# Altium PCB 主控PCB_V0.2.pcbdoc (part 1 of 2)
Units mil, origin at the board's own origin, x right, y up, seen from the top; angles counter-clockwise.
Board outline 2407.32 x 1620 mil, 2 copper layers (Top Layer, Bottom Layer); 44 components, 39 nets, 171 pads, 174 vias.
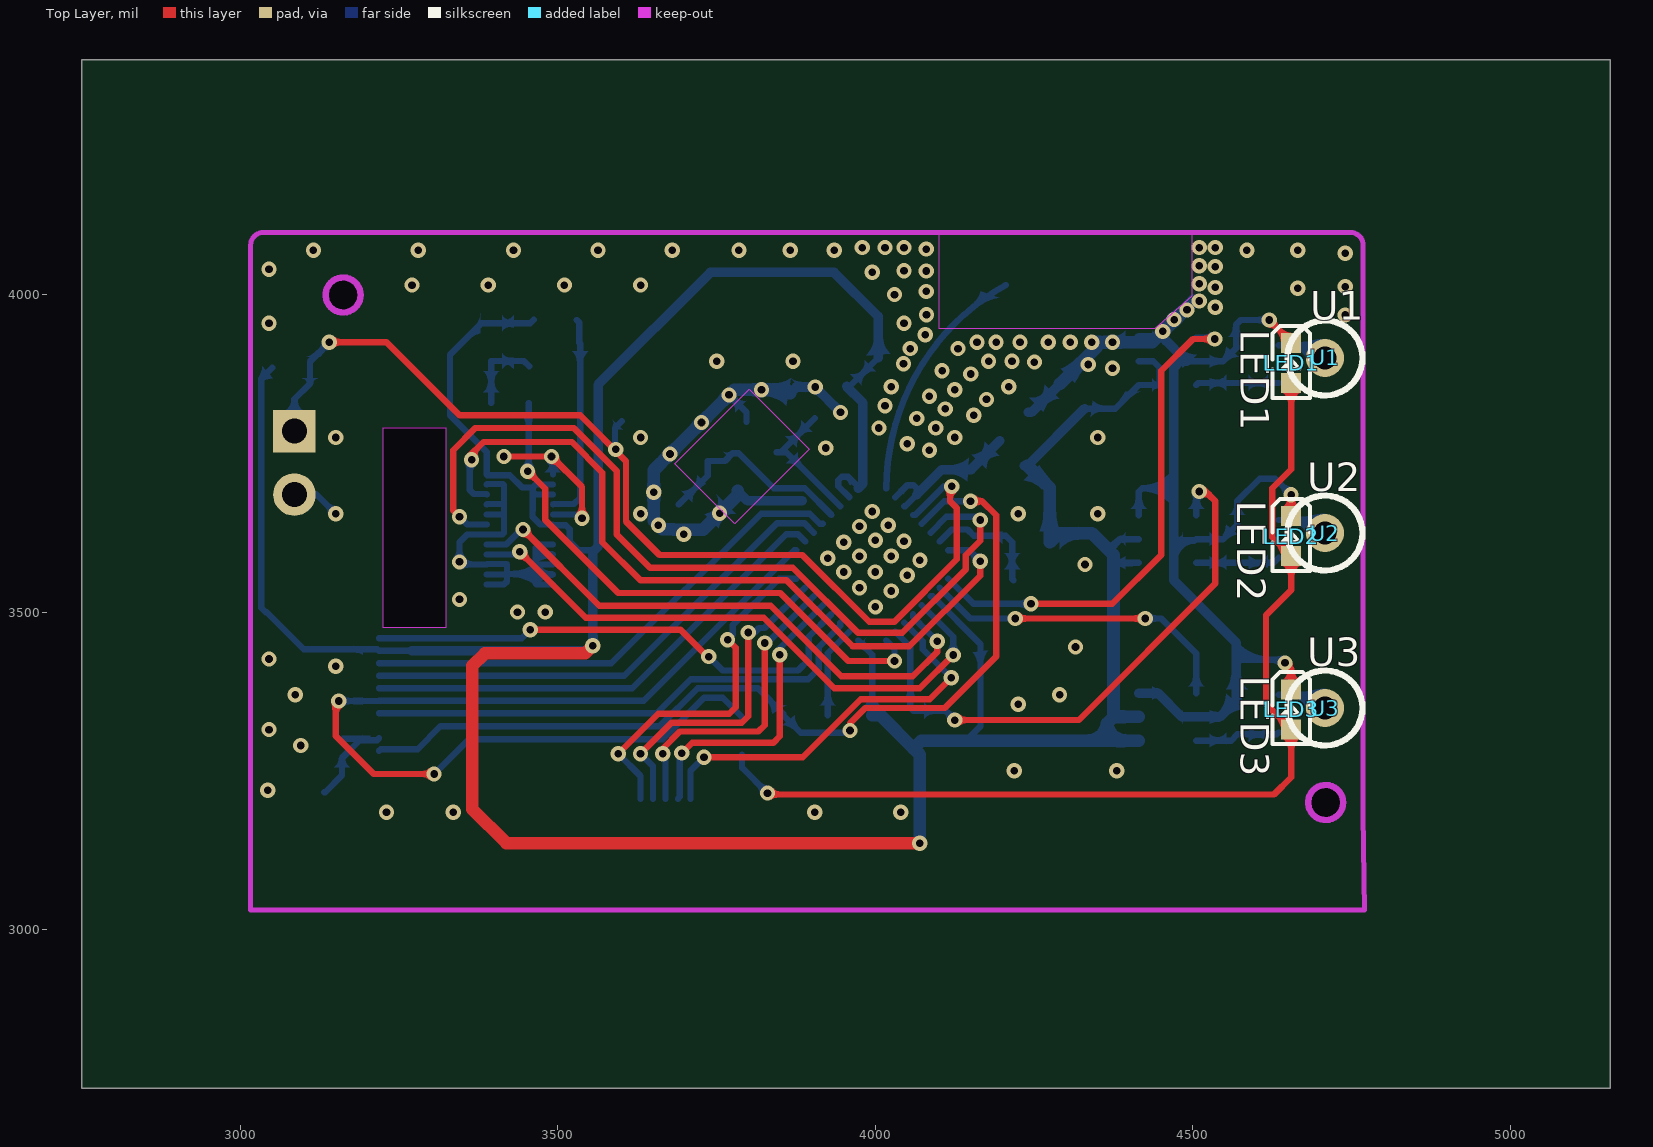
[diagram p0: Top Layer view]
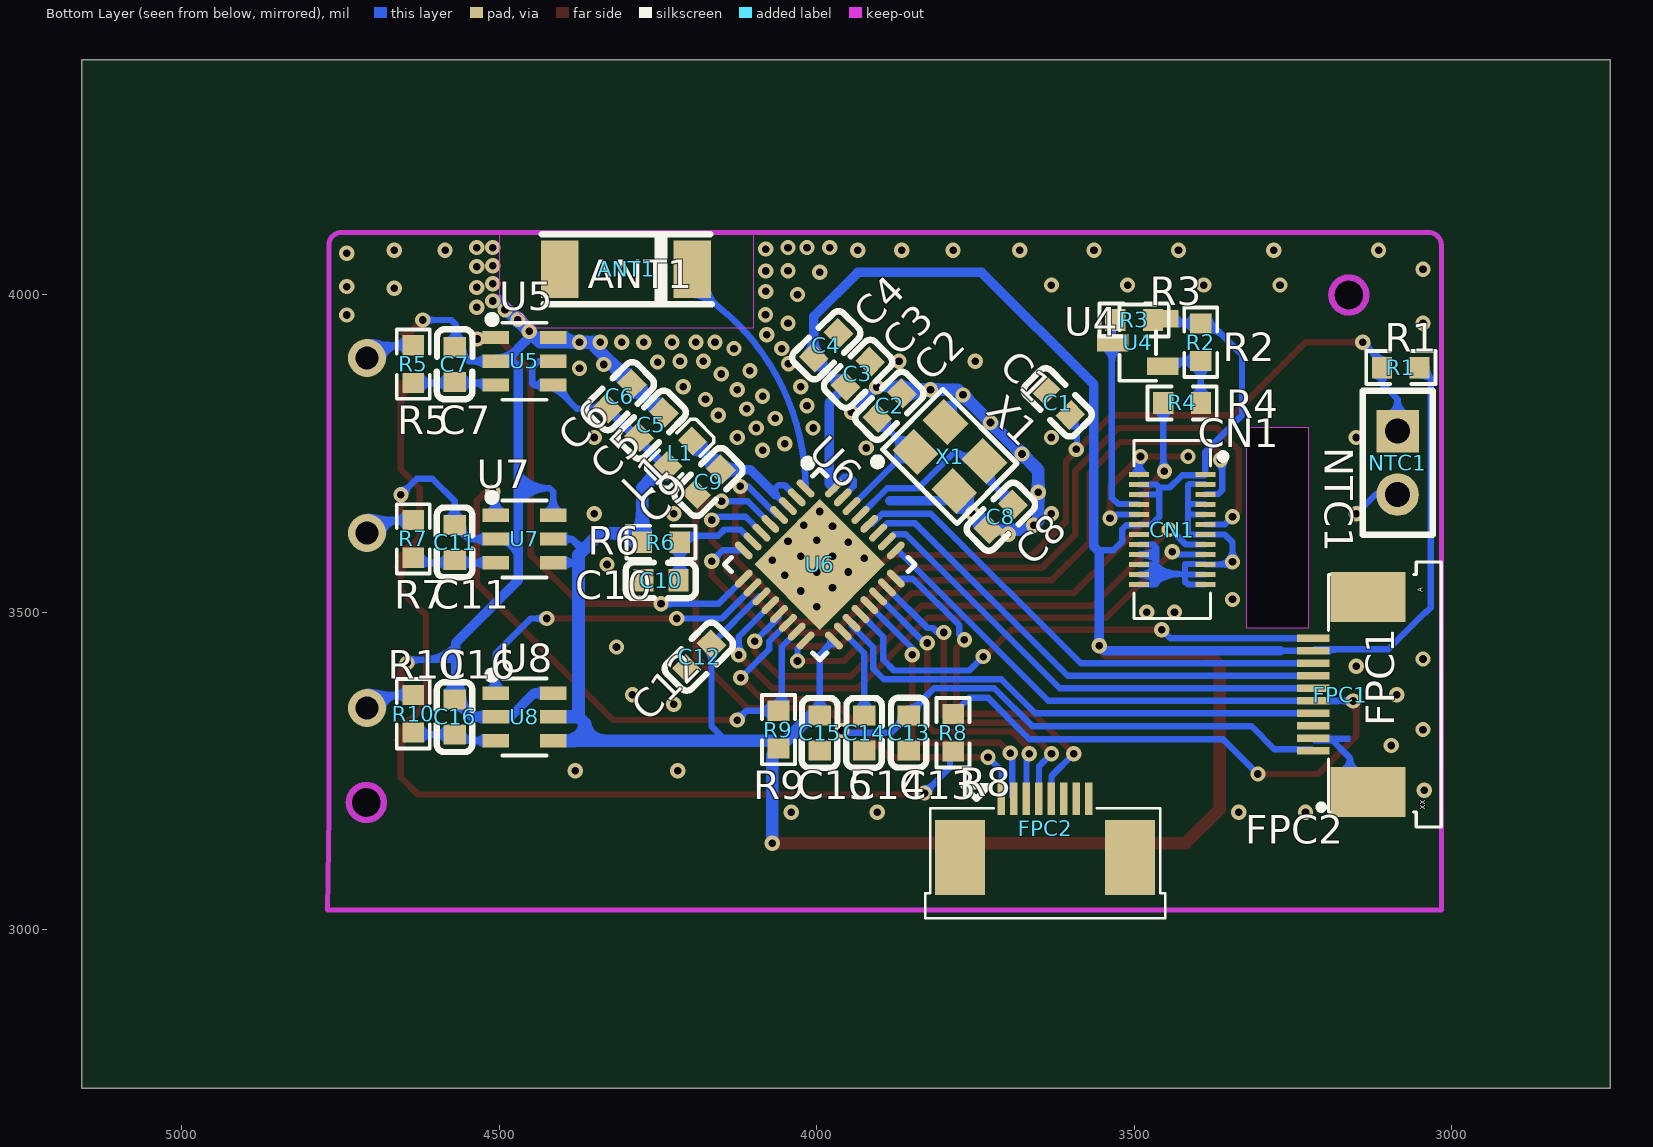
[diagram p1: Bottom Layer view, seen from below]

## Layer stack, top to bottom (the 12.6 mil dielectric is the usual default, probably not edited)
Top Layer: signal copper (thickness not stored)
Dielectric: dielectric 12.6, FR-4, Dk 4.8
Bottom Layer: signal copper (thickness not stored)

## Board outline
5157.32,2750 2750,2750 2750,4370 5157.32,4370
cut-out: 4736.57,3200.19 ccw(c4709.02,3199.82) 4681.46,3200.19 ccw(c4709.02,3200.56)
cut-out: 3189.33,3999.4 ccw(c3161.77,3999.4) 3134.21,3999.4 ccw(c3161.77,3999.4)
cut-out: 3225,3790 3323.43,3790 3323.43,3475.04 3225,3475.04

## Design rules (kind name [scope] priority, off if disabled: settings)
BoardOutlineClearance copperThickness1oz [All] p0: genericclearance=10 ignorepadtopadclearanceinfootprint=FALSE except(0: Arc-SplitContinuation Track-SplitContinuation SMDPad-SplitContinuation THPad-SplitContinuation Via-SplitContinuation Fill-SplitContinuation Poly-SplitContinuation Region-SplitContinuation Text-SplitContinuation; 6: Track-CutoutEdge SMDPad-CutoutEdge THPad-CutoutEdge Via-CutoutEdge Region-CutoutEdge; 11.8: Track-OutlineEdge SMDPad-OutlineEdge THPad-OutlineEdge Via-OutlineEdge Fill-OutlineEdge Region-OutlineEdge Poly-OutlineEdge Text-OutlineEdge Fill-CutoutEdge)
BoardOutlineClearance copperThickness2oz [All] p0: genericclearance=10 ignorepadtopadclearanceinfootprint=FALSE except(0: Arc-SplitContinuation Track-SplitContinuation SMDPad-SplitContinuation THPad-SplitContinuation Via-SplitContinuation Fill-SplitContinuation Poly-SplitContinuation Region-SplitContinuation Text-SplitContinuation; 6: Track-CutoutEdge SMDPad-CutoutEdge THPad-CutoutEdge Via-CutoutEdge Region-CutoutEdge; 11.8: Track-OutlineEdge SMDPad-OutlineEdge THPad-OutlineEdge Via-OutlineEdge Fill-OutlineEdge Region-OutlineEdge Poly-OutlineEdge Text-OutlineEdge Fill-CutoutEdge)
Clearance copperThickness1oz [(InNet('$1N1219') OR InNet('GND') OR InNet('3V3') OR InNet('$1N1185') OR InNet('$1N1981') OR InNet('$1N1223') OR InNet('$1N1184') OR InNet('CHIP_EN') OR InNet('VDD_SPI') OR InNet('$1N1977') OR InNet('$1N1980') OR InNet('GPIO0') OR InNet('GPIO6') OR InNet('GPIO7') OR InNet('GPIO2') OR InNet('K') OR InNet('GPIO3') OR InNet('ADC_VIN') OR InNet('ESP_TX') OR InNet('ESP_RX') OR InNet('GPIO13') OR InNet('GPIO12') OR InNet('DN1') OR InNet('DP1') OR InNet('$1N3691') OR InNet('$1N1982') OR InNet('$1N1983') OR InNet('$1N1984') OR InNet('GPIO9') OR InNet('$1N1544') OR InNet('BL') OR InNet('GPIO4') OR InNet('GPIO5') OR InNet('$1N7080') OR InNet('GPIO8') OR InNet('GPIO14') OR InNet('GPIO15') OR InNet('GPIO16') OR InNet('GPIO17'))] p1: gap=7 ignorepadtopadclearanceinfootprint=FALSE except(4: Track-Track; 6: Track-SMDPad SMDPad-SMDPad Track-THPad SMDPad-THPad THPad-THPad Track-Via SMDPad-Via THPad-Via Via-Via SMDPad-Fill THPad-Fill Via-Fill Fill-Fill Track-Region SMDPad-Region THPad-Region Via-Region Region-Region Track-Poly SMDPad-Poly THPad-Poly Via-Poly Fill-Poly Region-Poly Poly-Poly Track-Text SMDPad-Text THPad-Text Via-Text Fill-Text Region-Text Poly-Text Text-Text; 6.9: Track-Hole SMDPad-Hole THPad-Hole Via-Hole Fill-Hole Region-Hole Poly-Hole Text-Hole Sheet-Hole; 11.8: Track-Fill Fill-Region Track-Sheet SMDPad-Sheet THPad-Sheet Via-Sheet Fill-Sheet Region-Sheet Poly-Sheet Text-Sheet)
Clearance copperThickness2oz [All] p1: gap=7 ignorepadtopadclearanceinfootprint=FALSE except(6: Track-SMDPad SMDPad-SMDPad Track-THPad SMDPad-THPad THPad-THPad Track-Via SMDPad-Via THPad-Via Via-Via SMDPad-Fill THPad-Fill Via-Fill Fill-Fill Track-Region SMDPad-Region THPad-Region Via-Region Region-Region Track-Poly SMDPad-Poly THPad-Poly Via-Poly Fill-Poly Region-Poly Poly-Poly Track-Text SMDPad-Text THPad-Text Via-Text Fill-Text Region-Text Poly-Text Text-Text; 6.9: Track-Hole SMDPad-Hole THPad-Hole Via-Hole Fill-Hole Region-Hole Poly-Hole Text-Hole Sheet-Hole; 8: Track-Track; 11.8: Track-Fill Fill-Region Track-Sheet SMDPad-Sheet THPad-Sheet Via-Sheet Fill-Sheet Region-Sheet Poly-Sheet Text-Sheet)
DiffPairsRouting differentialPair [All] p1: maxuncoupledlength=10 minlimit=6 maxlimit=6 mostfreqgap=6 toplayer_minwidth=5 toplayer_prefwidth=10 toplayer_maxwidth=100 bottomlayer_minwidth=5 bottomlayer_prefwidth=10 bottomlayer_maxwidth=100
PasteMaskExpansion pasteMaskExpansion [All] p1: expansion=0
PlaneConnect innerPlane [All] p1: planeconnectstyle=Relief reliefexpansion=20 reliefentries=4 reliefconductorwidth=10 reliefairgap=10
PolygonConnect copperRegion [All] p1: connectstyle=Relief reliefentries=4 reliefconductorwidth=10 polygonreliefangle="90 Angle" airgapwidth=10
RoutingVias viaSize [All] p1: viastyle="Through Hole" holewidth=12.0078 minholewidth=11.811 maxholewidth=248.0314 width=24.0158 minwidth=19.685 maxwidth=393.7008
SolderMaskExpansion solderMaskExpansion [All] p1: useseparateexpansions=TRUE expansion=2 expansionbottom=2
Width copperThickness1oz [All] p1: maxlimit=100 minlimit=5 preferedwidth=10
Width copperThickness2oz [All] p1: maxlimit=100 minlimit=8 preferedwidth=10

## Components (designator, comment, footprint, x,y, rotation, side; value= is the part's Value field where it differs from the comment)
ANT1 "CA-C03" ANT-SMD_CA-C03 4300,4040 r180 bottom
C1 "CAP_0603" C0603 3620,3830 r225 bottom
C2 "CAP_0402" C0603 3885,3825 r135 bottom
C3 "CC0603KRX7R9BB104" C0603 3935,3875 r315 bottom
C4 "CL10A106MQ8NNNC" C0603 3985,3920 r315 bottom
C5 "CL10A105KB8NNNC" C0603 4260,3795 r315 bottom
C6 "CL10A106MQ8NNNC" C0603 4310,3840 r315 bottom
C7 "CAP_0603" C0603 4570,3890 r270 bottom
C8 "CAP_0402" C0603 3710,3650 r315 bottom
C9 "CC0603KRX7R9BB104" C0603 4170,3705 r135 bottom
C10 "CL10A105KB8NNNC" C0603 4245,3550 r180 bottom
C11 "CAP_0603" C0603 4570,3610 r90 bottom
C12 "CC0603KRX7R9BB104" C0603 4185,3430 r135 bottom
C13 "CAP_0603" C0603 3855,3310 r270 bottom
C14 "CL10A106MQ8NNNC" C0603 3925,3310 r90 bottom
C15 "CC0603KRX7R9BB104" C0603 3995,3310 r90 bottom
C16 "CAP_0603" C0603 4570,3335 r90 bottom
CN1 "DF37NC-24DS-0.4V(51)" CONN-SMD_DF37NC-24DS-0.4V-51 3440,3630 r270 bottom locked
FPC1 "F0501-T-10-20T-R" FPC-SMD_F0501-T-10-20T-R 3175,3370 r90 bottom locked
FPC2 "F0501-T-08-20T-R" FPC-SMD_8P-P0.50_L4.4-W9.6 3640,3160 r180 bottom
L1 "L_0402" l0603 4215,3750 r135 bottom
LED1 "LED_0603-B" LED_0603 4655,3890 r270 top locked
LED2 "LED_0603-B" LED_0603 4655,3617.5 r270 top locked
LED3 "LED_0603-B" LED_0603 4655,3345 r270 top locked
NTC1 "HDR-F_2.54_1x2P" HDR-TH_2P-P2.54-V-F 3085,3735 r270 bottom
R1 "Res_0603" R0603 3080,3885 r180 bottom
R2 "Res_0402" R0603 3395,3925 r270 bottom
R3 "Res_0402" R0603 3500,3960 r0 bottom
R4 "Res_0402" R0603 3424.33,3829.34 r180 bottom
R5 "Res_0603" R0603 4635,3890.56 r270 bottom
R6 "Res_0603" R0603 4245,3610 r180 bottom
R7 "Res_0603" R0603 4635,3615.28 r270 bottom
R8 "Res_0603" R0603 3785,3310 r270 bottom
R9 "Res_0603" R0603 4060,3315 r90 bottom
R10 "Res_0603" R0603 4635,3340 r270 bottom
U1 "触摸弹簧 H10.0mm" TH_H10.0MM 4707.91,3900.16 r0 top locked
U2 "触摸弹簧 H10.0mm" TH_H10.0MM 4707.91,3624.57 r0 top locked
U3 "触摸弹簧 H10.0mm" TH_H10.0MM 4707.91,3348.98 r0 top locked
U4 "AO3401A" SOT-23-3_L2.9-W1.3-P1.90-LS2.4-BR 3494.2,3924.34 r180 bottom
U5 "JL423B" SOT-23-6_L2.9-W1.6-P0.95-LS2.8-BL-2 4460,3895 r270 bottom
U6 "ESP32-C3FN4" QFN-32_L5.0-W5.0-P0.50-BL-EP3.7 3995,3575 r315 bottom locked
U7 "JL423B" SOT-23-6_L2.9-W1.6-P0.95-LS2.8-BL-2 4460,3615 r270 bottom
U8 "JL423B" SOT-23-6_L2.9-W1.6-P0.95-LS2.8-BL-2 4460,3335 r270 bottom
X1 "X322540MPB4SI" OSC-SMD_4P-L3.2-W2.5-BL_SIT8008BI 3790,3745 r225 bottom

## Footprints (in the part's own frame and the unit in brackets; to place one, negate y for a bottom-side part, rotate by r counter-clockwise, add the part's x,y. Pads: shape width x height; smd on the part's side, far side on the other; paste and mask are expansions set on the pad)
ANT-SMD_CA-C03 [mm]
  rect 1.5x2.3 smd: 1(-2.65,0) 2(2.65,0)
  silkscreen extent -3.37,-1.4 3.43,1.4
C0603 [mm]
  rect 0.8x0.9 smd: 1(-0.7,0) 2(0.7,0)
  silkscreen extent -1.41,-0.71 1.39,0.72
CONN-SMD_DF37NC-24DS-0.4V-51 [mm]
  rect 0.2x0.8 smd: 1(-2.2,1.325) 2(-2.2,-1.325) 3(-1.8,1.325) 4(-1.8,-1.325) 5(-1.4,1.325) 6(-1.4,-1.325) 7(-1,1.325) 8(-1,-1.325) 9(-0.6,1.325) 10(-0.6,-1.325) 11(-0.2,1.325) 12(-0.2,-1.325) 13(0.2,1.325) 14(0.2,-1.325) 15(0.6,1.325) 16(0.6,-1.325) 17(1,1.325) 18(1,-1.325) 19(1.4,1.325) 20(1.4,-1.325) 21(1.8,1.325) 22(1.8,-1.325) 23(2.2,1.325) 24(2.2,-1.325)
  silkscreen extent -3.56,-1.52 3.56,2.16
FPC-SMD_8P-P0.50_L4.4-W9.6 [mm]
  rect 2x3 smd: 0(-3.4,-1.175) 0(3.4,-1.175)
  rect 0.3x1.3 smd: 1(-1.75,1.175) 2(-1.25,1.175) 3(-0.75,1.175) 4(-0.25,1.175) 5(0.25,1.175) 6(0.75,1.175) 7(1.25,1.175) 8(1.75,1.175)
  silkscreen extent -4.8,-3.6 4.8,1.68
FPC-SMD_F0501-T-10-20T-R [mm]
  rect 0.3x1.3 smd: 1(-2.25,1.097) 2(-1.75,1.097) 3(-1.25,1.097) 4(-0.75,1.097) 5(-0.25,1.097) 6(0.25,1.097) 7(0.75,1.097) 8(1.25,1.097) 9(1.75,1.097) 10(2.25,1.097)
  rect 2x3 smd: 11(3.9,-1.097) 12(-3.9,-1.097)
  silkscreen extent -5.3,-4.03 5.3,0.87
HDR-TH_2P-P2.54-V-F [mm]
  rect 1.7x1.7 hole 1: 1(-1.27,0)
  round 1.7 hole 1: 2(1.27,0)
  silkscreen extent -2.88,-1.39 2.88,1.4
l0603 [mm]
  rect 0.8x0.864 smd: 1(-0.7,0) 2(0.7,0)
  silkscreen extent -1.42,-0.65 1.41,0.67
LED_0603 [mil]
  rect 31.5x31.5 smd: 1(-33.5,-0.4) 2(29.5,-0.2)
  silkscreen extent -61,-30 53,30
OSC-SMD_4P-L3.2-W2.5-BL_SIT8008BI [mm]
  rect 1.4x1.2 smd: 1(-1.1,-0.85) 2(1.1,-0.85) 3(1.1,0.85) 4(-1.1,0.85)
  silkscreen extent -2.1,-2.35 2.1,1.7
QFN-32_L5.0-W5.0-P0.50-BL-EP3.7 [mm]
  oval 0.28x0.9 smd: 1(-1.75,-2.55) 2(-1.25,-2.55) 3(-0.749,-2.55) 4(-0.249,-2.55) 5(0.249,-2.55) 6(0.749,-2.55) 7(1.25,-2.55) 8(1.75,-2.55) 17(1.75,2.55) 18(1.25,2.55) 19(0.749,2.55) 20(0.249,2.55) 21(-0.249,2.55) 22(-0.749,2.55) 23(-1.25,2.55) 24(-1.75,2.55)
  oval 0.9x0.28 smd: 9(2.55,-1.75) 10(2.55,-1.25) 11(2.55,-0.749) 12(2.55,-0.249) 13(2.55,0.249) 14(2.55,0.749) 15(2.55,1.25) 16(2.55,1.75) 25(-2.55,1.75) 26(-2.55,1.25) 27(-2.55,0.749) 28(-2.55,0.249) 29(-2.55,-0.249) 30(-2.55,-0.749) 31(-2.55,-1.25) 32(-2.55,-1.75)
  rect 3.7x3.7 smd: 33(0,0)
  silkscreen extent -2.7,-3.35 2.7,2.7
R0603 [mil]
  rect 31.75x34.02 smd: 1(-29.66,0) 2(29.66,0)
  silkscreen extent -55,-26 55,26
SOT-23-3_L2.9-W1.3-P1.90-LS2.4-BR [mm]
  rect 1.25x0.7 smd: 1(1,-0.95) 2(1,0.95) 3(-1,0)
  silkscreen extent -0.73,-1.53 0.73,1.53
SOT-23-6_L2.9-W1.6-P0.95-LS2.8-BL-2 [mil]
  rect 20.95x42.2 smd: 1(-37.4,-45.24) 2(0,-45.24) 3(37.4,-45.24) 4(37.4,45.24) 5(0,45.24) 6(-37.4,45.24)
  silkscreen extent -72,-57 61,35
TH_H10.0MM [mil]
  round 60 hole 36: 1(0,0)
  silkscreen extent -59,-59 59,59

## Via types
v1: diameter 24.02, hole 12.01, Top Layer to Bottom Layer, 174 vias

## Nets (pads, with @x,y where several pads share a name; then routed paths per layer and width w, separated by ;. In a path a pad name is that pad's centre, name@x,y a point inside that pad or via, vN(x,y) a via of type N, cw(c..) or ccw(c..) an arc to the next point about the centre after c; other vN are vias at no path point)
3V3: C3.2 C4.2 C5.2 C6.2 C12.2 C15.2 CN1.1 CN1.4 CN1.6 CN1.12 FPC1.9 L1.1 R1.2 R2.1 R3.1 R6.1 R9.1 U4.2 U5.4 U5.5 U6.11 U6.17 U6.31 U6.32 U7.4 U7.5 U8.4 U8.5 | length 6142.6
  Top Layer w20: v1(3555,3447.21) 3542.79,3435 3385,3435 3365,3415 3365,3190 3418.82,3136.18 v1(4069.85,3136.18)
  Bottom Layer w10: 3032.92,3867.58 R1.2@3050.34,3885 ; 3032.93,3867.58 3032.93,3507.07 3040,3500 3041.41,3500 3099.71,3441.7 3215.38,3441.7 FPC1.9@3218.18,3438.89 3270,3438.89 ; R3.1@3462.13,3960.14 3456.64,3954.66 3379.66,3954.66 3330,3905 3330,3810 3387.84,3752.16 CN1.1@3387.84,3716.61 3388.66,3715.79 3424.21,3715.79 3443.75,3696.25 3460.39,3696.25 ; CN1.6@3492.16,3685.11 3465,3685.11 3460.39,3689.73 ; CN1.4@3492.16,3700.86 3465,3700.86 3460.39,3696.25 ; 3557.5,3597.5 3532.54,3597.5 3518.9,3611.14 3518.9,3630.61 3512.46,3637.05 3492.99,3637.05 CN1.12@3492.16,3637.88 3472.12,3637.88 3460,3650 3460,3660 3460.39,3660.39 3460.39,3689.73 ; C3.2@3954.49,3855.51 3959.49,3855.51 C4.2@4004.49,3900.51 ; U6.31@3958.8,3680.78 3958.8,3681.2 3941.59,3698.41 3941.59,3707.45 3947.07,3712.93 3957.07,3712.93 3972.73,3697.27 U6.32@3972.73,3694.71 ; U6.17@3972.73,3455.29 3995,3433.01 C15.2@3995,3340 ; U6.11@4086.85,3524.87 4090.13,3524.87 C12.2@4165.51,3449.49 4165.51,3320.51 4142.6,3297.6 ; C6.2@4329.49,3820.51 4377.67,3820.51 U5.4@4414.76,3857.6 4445.2,3857.6 4447.6,3860 4447.6,3885 4437.6,3895 U5.5@4414.76,3895 ; 4366.57,3598.43 4368.43,3598.43 4385,3615 U7.5@4414.76,3615 ; 4375,3577.05 4375.55,3577.6 U7.4@4414.76,3577.6 ; 3460.39,3689.73 3460.39,3696.25
  Bottom Layer w15: 3270,3438.89 3546.69,3438.89 v1(3555,3447.21) 3555,3595 3557.5,3597.5 3563.36,3603.36 3563.36,3858.36 3740,4035 3935,4035 4004.49,3965.51 C4.2@4004.49,3900.51 ; C3.2@3954.49,3855.51 3980,3830 3980,3701.99 U6.32@3972.73,3694.71 ; C15.2@3995,3337.56 C15.2@3995,3340 ; L1.1@4234.48,3730.52 4239.49,3730.52 C6.2@4329.49,3820.51
  Bottom Layer w20: C15.2@3995,3337.56 4007.78,3337.56 R9.1@4060,3285.34 ; v1(4069.85,3136.18) 4069.85,3275.49 R9.1@4060,3285.34 ; L1.1@4239.49,3730.52 4274.66,3695.35 R6.1@4274.66,3610 4288.8,3624.14 4340.86,3624.14 4366.57,3598.43 4375,3590 4375,3577.05 4375,3335 ; U8.4@4414.76,3297.6 4364.65,3297.6 ; U8.5@4414.76,3335 4375,3335 ; R9.1@4060,3285.34 4060.34,3285.34 4072.6,3297.6 4142.6,3297.6 4364.65,3297.6 ; 4364.65,3297.6 4364.65,3324.65 4375,3335
$1N1184: C8.1 U6.29 X1.3 | length 327.7
  Bottom Layer w10: C8.1@3690.51,3669.49 3735.71,3714.69 X1.3@3735.71,3738.04 3763.04,3738.04 3775,3750 3785,3750 3840,3695 3888.86,3695 U6.29@3930.94,3652.92
$1N1185: C2.1 U6.30 X1.1 | length 211.6
  Bottom Layer w10: X1.1@3844.29,3751.96 X1.1@3850.94,3751.96 ; C2.1@3904.49,3805.51 X1.1@3850.94,3751.96 ; U6.30@3944.87,3666.85 3859.76,3751.96 X1.1@3850.94,3751.96
$1N1219: ANT1.2 U6.1 | length 389.2
  Bottom Layer w10: U6.1@4017.27,3694.71 cw(c4384.36,3694.71) ANT1.2@4205,4015
$1N1223: C9.2 L1.2 U6.2 U6.3 | length 246.7
  Bottom Layer w10: U6.2@4031.2,3680.78 4050.42,3700 4060,3700 4065,3695 4065,3685 4046.85,3666.85 U6.3@4045.13,3666.85
  Bottom Layer w15: 4065,3685 4104.49,3724.49 C9.2@4150.51,3724.49 L1.2@4195.52,3769.48
$1N1544: R2.2 R4.2 U4.1 | length 129.4
  Bottom Layer w10: R4.2@3394.67,3829.34 3395,3829.68 R2.2@3395,3895.34 3446.43,3895.34 U4.1@3454.83,3886.94
$1N1977: C7.2 R5.2 U5.3 | length 131.1
  Bottom Layer w10: U5.3@4505.24,3857.6 4508.54,3860.9 R5.2@4635,3860.9
$1N1980: C16.1 R10.2 U8.3 | length 135
  Bottom Layer w10: U8.3@4505.24,3297.6 4560.16,3297.6 C16.1@4570,3307.44 4632.1,3307.44 R10.2@4635,3310.34
$1N1981: C11.1 R7.2 U7.3 | length 133.1
  Bottom Layer w10: U7.3@4505.24,3577.6 4626.98,3577.6 R7.2@4635,3585.62
$1N1982: R5.1 U1.1 | length 81.2
  Bottom Layer w10: R5.1@4635,3920.22 4687.85,3920.22 U1.1@4707.91,3900.16
$1N1983: R10.1 U3.1 | length 81.5
  Bottom Layer w10: R10.1@4635,3369.66 4687.23,3369.66 U3.1@4707.91,3348.98
$1N1984: R7.1 U2.1 | length 81.4
  Bottom Layer w10: R7.1@4635,3644.94 4687.54,3644.94 U2.1@4707.91,3624.57
$1N3691: LED1.2 LED2.2 LED3.2 R8.2 | length 1592.2
  Top Layer w10: v1(3830,3215) 3832.3,3212.7 4627.7,3212.7 4654.8,3239.8 LED3.2@4654.8,3315.5 4615,3355.3 4615,3495 4654.8,3534.8 LED2.2@4654.8,3588 4625,3617.8 4625,3695 4654.8,3724.8 LED1.2@4654.8,3860.5
  Bottom Layer w10: R8.2@3790,3275.34 3790,3255 v1(3830,3215)
$1N7080: FPC1.3
ADC_VIN: C13.1 FPC1.1 U6.5 | length 1463
  Top Layer w10: v1(3960,3313.65) 3960,3325 3983.98,3348.98 4108.98,3348.98 4190,3430 4190,3652.52 4167.77,3674.75 v1(4149.75,3674.75)
  Bottom Layer w10: FPC1.1@3218.18,3281.41 3220.98,3284.22 3279.22,3284.22 3315,3320 3660,3320 3720,3380 3815,3380 3855,3340 C13.1@3855,3337.56 3882.56,3310 3956.35,3310 v1(3960,3313.65) ; U6.5@4072.92,3639.06 4108.61,3674.75 v1(4149.75,3674.75)
BL: R4.1 U6.16 | length 876
  Top Layer w10: v1(3452.29,3721.87) 3480,3694.15 3480,3645 3595,3530 3850,3530 3957.01,3422.99 v1(4030,3422.99)
  Bottom Layer w10: v1(3452.29,3721.87) 3453.99,3723.57 R4.1@3453.99,3829.34 ; U6.16@4017.27,3455.29 4030,3442.56 v1(4030,3422.99)
CHIP_EN: C10.2 R6.2 U6.7 | length 191.5
  Bottom Layer w10: U6.7@4100.78,3611.2 4101.2,3611.2 4120,3630 4145,3630 4155,3620 4205.34,3620 R6.2@4215.34,3610 4215.34,3552.1 C10.2@4217.44,3550
DN1: FPC1.5 R8.1 U6.25 | length 1602.8
  Top Layer w10: v1(3155,3360) 3150,3355 3150,3305 3210,3245 v1(3305,3245)
  Bottom Layer w10: v1(3155,3360) 3218.02,3360 FPC1.5@3218.18,3360.16 3635.16,3360.16 3872.27,3597.27 U6.25@3875.29,3597.27 ; v1(3305,3245) 3360,3300 3665,3300 3730,3365 3759.66,3365 R8.1@3790,3334.66
DP1: FPC1.6 U6.26 | length 776.1
  Bottom Layer w10: FPC1.6@3218.18,3379.84 3617.27,3379.84 3859.82,3622.4 3878.02,3622.4 U6.26@3889.22,3611.2
ESP_RX: FPC1.7 U6.27 | length 790.7
  Bottom Layer w10: FPC1.7@3218.18,3399.53 3604.53,3399.53 3845,3640 3888.28,3640 U6.27@3903.15,3625.13
ESP_TX: FPC1.8 U6.28 | length 803.2
  Bottom Layer w10: FPC1.8@3218.18,3419.22 3584.22,3419.22 3820,3655 3896.61,3655 3912.55,3639.06 U6.28@3917.08,3639.06
GND: C1.1 C2.2 C3.1 C4.1 C5.1 C6.1 C7.1 C8.2 C9.1 C10.1 C11.2 C12.1 C13.2 C14.1 C15.1 C16.2 CN1.2 CN1.3 CN1.7 CN1.9 CN1.10 CN1.13 CN1.16 CN1.18 CN1.19 CN1.20 CN1.21 CN1.22 CN1.23 CN1.24 FPC1.2 FPC1.11 FPC1.12 FPC2.0 LED1.1 LED2.1 LED3.1 NTC1.2 U5.2 U5.6 U6.33 U7.2 U7.6 U8.2 U8.6 X1.2 X1.4 | length 3883.7
  Top Layer w10: v1(3415,3745) v1(3490,3745) 3537.87,3697.13 v1(3537.87,3647.85) ; v1(4620,3960) 4654.6,3925.4 LED1.1@4654.6,3923.5 ; v1(4645,3420) 4654.6,3410.4 LED3.1@4654.6,3378.5 ; LED2.1@4654.6,3651 v1(4654.6,3685)
  Top Layer w20: v1(4225,3655) v1@4225.08,3654.92
  Bottom Layer w10: NTC1.2@3085,3685 3120.12,3685 v1(3150.2,3654.92) ; FPC1.12@3131.82,3216.45 3133.53,3216.45 3160,3242.93 3160,3270.27 3188.04,3298.3 3215.38,3298.3 FPC1.2@3218.18,3301.11 ; CN1.23@3387.84,3543.39 3415,3543.39 3419.87,3548.25 3419.87,3560.06 ; CN1.21@3387.84,3559.14 3418.94,3559.14 3419.87,3560.06 ; CN1.9@3387.84,3653.62 3413.62,3653.62 3415,3655 ; CN1.7@3387.84,3669.38 3388.65,3670.19 3414.81,3670.19 3415,3670 ; CN1.3@3387.84,3700.86 3388.66,3701.69 3413.31,3701.69 3415,3700 3415,3670 ; 3419.93,3560 3464.94,3560 ; 3464.94,3545.06 3464.94,3560 ; 3464.94,3574.89 3464.94,3560 ; 3465,3545 3466.61,3543.39 CN1.24@3492.16,3543.39 ; 3465.2,3580.1 3465.2,3601.58 3470,3606.38 CN1.16@3492.16,3606.38 ; 3465.86,3559.14 CN1.22@3492.16,3559.14 ; 3465.84,3590.64 CN1.18@3492.16,3590.64 ; 3470,3574.89 CN1.20@3492.16,3574.89 ; v1(3490,3745) 3492.16,3742.84 CN1.2@3492.16,3716.61 ; CN1.10@3492.16,3653.62 3532.1,3653.62 v1(3537.87,3647.85) ; v1(3769.52,3842.02) 3796.96,3814.58 X1.4@3796.96,3799.29 ; U7.6@4414.76,3652.4 4414.76,3689.76 4420,3695 4467.58,3695 4470,3692.58 ; 4470,3620 4477.07,3612.93 4503.17,3612.93 U7.2@4505.24,3615 4547.44,3615 C11.2@4570,3637.56 4570,3675 4605,3710 4629.6,3710 v1(4654.6,3685) ; U5.2@4490,3895 U5.2@4505.24,3895 4547.44,3895 C7.1@4570,3917.56 4567.93,3919.63 4567.93,3952.93 4575,3960 v1(4620,3960) ; 4567.93,3417.93 4575,3425 4640,3425 v1(4645,3420) ; 3415,3655 3415,3670 ; 3415,3655 3415,3625 3412.12,3622.12 CN1.13@3387.84,3622.12 3357.12,3622.12 3345,3610 v1(3345,3579.03) 3349.14,3574.89 CN1.19@3387.84,3574.89 3388.66,3575.71 3419.15,3575.71 3419.87,3575 3419.87,3560.06
  Bottom Layer w15: X1.2@3783.04,3690.71 3798.75,3675 3885,3675 ; C2.2@3865.51,3844.49 3875.51,3854.49 v1(3905.21,3854.49) 3905.21,3854.29 v1(3945.06,3814.44) ; C5.1@4240.51,3814.49 4245.51,3814.49 C6.1@4290.51,3859.49 ; U8.6@4414.76,3372.4 4445,3372.4 4482.4,3335 U8.2@4505.24,3335 4542.44,3335 C16.2@4570,3362.56 4567.93,3364.63 4567.93,3417.93 4567.93,3452.07 4470,3550 4470,3620 4470,3692.58 4470,3885 4480,3895 4490,3895 4452.6,3932.4 4442.98,3932.4 U5.6@4414.76,3932.4
  Bottom Layer w20: X1.2@3783.04,3690.71 3783.04,3684.06 v1(3754.62,3655.64) C8.2@3729.49,3630.51 3728.82,3629.84 3682.5,3629.84 3681.83,3630.51 3664.49,3630.51 3650.86,3644.14 v1(3650.86,3688.7) 3650.86,3723.36 v1(3676.42,3748.92) v1(3726.15,3798.65) v1(3769.52,3842.02) 3777.5,3850 v1(3820.55,3850) 3860,3850 C2.2@3865.51,3844.49 ; C6.1@4290.51,3859.49 v1@4348.43,3917.4 ; v1(4340.83,3925) v1(4373.35,3925) 4435.58,3925 4442.98,3932.4 v1(4452.6,3942.02) 4500.58,3990 v1(4510,3990)
  other v1: 3230,3185 3335,3185 3904.26,3185 4040,3185 3043.21,3219.55 4218.54,3250 4380,3250 3095,3290 3045,3315 4225,3355 3086.42,3370 4290,3370 3150.2,3414.92 3045,3426.12 4315,3445 3436.41,3500 3480,3500 4000,3508.24 3345,3520 4025,3533.24 3974.91,3538.24 4050,3558.24 3950,3563.24 3999.91,3563.24 4330,3575 4070,3581.76 3925,3585 3975,3588.24 4024.91,3588.24 3950,3610 4044.91,3611.76 4000,3613.24 3698.05,3622.44 3975,3635 3658.27,3636.73 4020,3636.76 3630.2,3654.92 4350.2,3654.92 3995,3658.52 4085,3755 3921.79,3758.47 4050,3765 3150.2,3774.92 3630.2,3774.92 4125,3775 4350.2,3774.92 4005.49,3789.95 4095,3790 4065,3805 4155,3810 4110,3820 4015,3825 4175,3835 4085,3840 4125,3850 4025,3855 4210,3855 4150,3875 4105,3880 4373.35,3883.83 4335,3890 4044.23,3891.07 4250.33,3893.68 3750.2,3894.92 3870.2,3894.92 4178.21,3895 4215,3895 4055,3915 4130,3915 4160,3925 4189.99,3925 4227.7,3925 4272.01,3925 4306.89,3925 4078.34,3936.61 3045,3955 4045,3955 4470.32,3960.6 4080.49,3968.29 4740,3967.89 4490.56,3975.86 4535,3980.01 4030,4000 4080,4005 4665,4010 4535,4011.31 4740,4012.65 3270.2,4014.92 3390.2,4014.92 3510.2,4014.92 3630.2,4014.92 4510,4017.02 3995,4035 4080,4037.23 4045,4037.56 3045,4040 4535,4044.12 4510,4045.3 4740,4065 3115,4070 3280,4070 3430,4070 3563.06,4070 3680,4070 3785,4070 3865.68,4070 3935,4070 4585,4070 4665,4070 4080,4071.64 3979.28,4074 4015,4074 4045,4074 4510,4074 4535,4074
GPIO0: C1.2 NTC1.1 R1.1 U6.4 | length 1679.1
  Top Layer w10: v1(3140,3925) 3230,3925 3345,3810 3535,3810 3607.21,3737.79 3607.21,3642.79 3660,3590 3885,3590 3990,3485 4030,3485 4127.99,3582.99 4127.99,3663.99 4117.5,3674.48 4117.5,3695.49 v1(4120,3697.99)
  Bottom Layer w10: NTC1.1@3085,3785 3085,3835 3109.66,3859.66 R1.1@3109.66,3885 3109.66,3894.66 v1(3140,3925) ; v1@3590,3755 3590,3790 C1.2@3600.51,3800.51 ; U6.4@4059.06,3652.92 4062.92,3652.92 4107.99,3697.99 v1(4120,3697.99)
  other v1: 3591.26,3756.26
GPIO2: CN1.11 U6.6 | length 1389.9
  Top Layer w10: v1(3345,3650) 3335,3660 3335,3755 3370,3790 3525,3790 3592.75,3722.25 3592.75,3622.25 3645,3570 3870,3570 3972.5,3467.5 4042.5,3467.5 4142.01,3567.01 4142.01,3589.52 4165,3612.52 v1(4165,3645)
  Bottom Layer w10: v1(3345,3650) 3357.12,3637.88 CN1.11@3387.84,3637.88 ; U6.6@4086.85,3625.13 4111.72,3650 4160,3650 v1(4165,3645)
GPIO3: CN1.5 U6.8 | length 1220.1
  Top Layer w10: v1(3364.09,3740) 3364.09,3749.09 3382.99,3767.99 3521.53,3767.99 3570,3719.52 3570,3610 3630,3550 3860,3550 3964.02,3445.98 4053.47,3445.98 4165,3557.52 v1(4165,3580)
  Bottom Layer w10: v1(3364.09,3740) 3361.1,3737.01 3361.1,3692.38 3367.54,3685.94 3387.01,3685.94 CN1.5@3387.84,3685.11 ; U6.8@4114.71,3597.27 4147.73,3597.27 v1(4165,3580)
GPIO4: U5.1 U6.9 | length 808.7
  Top Layer w10: v1(4245,3512.99) 4372.99,3512.99 4450,3590 4450,3880 4500,3930 v1(4534.29,3930)
  Bottom Layer w10: U6.9@4114.71,3552.73 4154.45,3512.99 v1(4245,3512.99) ; U5.1@4505.24,3932.4 4531.89,3932.4 v1(4534.29,3930)
GPIO5: U6.10 U8.1 | length 509.9
  Top Layer w10: v1(4220,3490) v1(4425,3490)
  Bottom Layer w10: U6.10@4100.78,3538.8 4149.58,3490 v1(4220,3490) ; v1(4425,3490) 4450,3490 4505.24,3434.76 U8.1@4505.24,3372.4
GPIO6: CN1.17 U6.12 | length 946.2
  Top Layer w10: v1(3440,3595) 3544.02,3490.98 3824.02,3490.98 3935,3380 4070,3380 v1(4122.5,3432.5)
  Bottom Layer w10: CN1.17@3387.84,3590.64 3435.64,3590.64 v1(3440,3595) ; U6.12@4072.92,3510.94 4122.5,3461.36 v1(4122.5,3432.5)
GPIO7: CN1.15 U6.13 | length 906.4
  Top Layer w10: v1(3445,3630) 3565,3510 3835,3510 3945.98,3399.02 4059.02,3399.02 4097.24,3437.24 v1(4097.24,3454.1)
  Bottom Layer w10: CN1.15@3387.84,3606.38 3418.86,3606.38 3442.48,3630 v1(3445,3630) ; U6.13@4059.06,3497.08 4059.06,3492.55 4070.26,3481.35 4070.26,3481.08 v1(4097.24,3454.1)
GPIO8: FPC2.1 U6.14 | length 632.2
  Top Layer w10: v1(3730,3271.5) 3885.34,3271.5 3976.83,3362.99 4085.48,3362.99 v1(4119.23,3396.75)
  Bottom Layer w10: FPC2.1@3708.89,3206.26 3708.89,3250.4 v1(3730,3271.5) ; U6.14@4045.13,3483.15 4074.25,3454.03 4074.25,3441.73 v1(4119.23,3396.75)
GPIO9: R9.2 U6.15 U7.1 | length 907.4
  Top Layer w10: v1(4125,3330) 4320,3330 4535,3545 4535,3675 4520,3690 v1(4510,3690)
  Bottom Layer w10: U6.15@4031.2,3469.22 4055,3445.42 4055,3349.66 R9.2@4060,3344.66 4110.34,3344.66 v1(4125,3330) ; U7.1@4505.24,3652.4 4505.24,3685.24 v1(4510,3690)
GPIO12: FPC1.4 U6.19 | length 808.2
  Bottom Layer w10: FPC1.4@3218.18,3340.47 3655.65,3340.47 3709.19,3394.02 3894.02,3394.02 3910.98,3410.98 3910.98,3444.73 3944.87,3478.62 U6.19@3944.87,3483.15
GPIO13: FPC1.10 U6.20 | length 802.9
  Top Layer w10: v1(3456.42,3472.05) 3692.95,3472.05 3735,3430 v1(3737.52,3430)
  Bottom Layer w10: FPC1.10@3218.18,3458.59 3442.96,3458.59 v1(3456.42,3472.05) ; v1(3737.52,3430) 3759.48,3408.03 3878.03,3408.03 3895,3425 3895,3461.14 U6.20@3930.94,3497.08
GPIO14: FPC2.2 U6.21 | length 474
  Top Layer w10: v1(3695,3277.99) 3711.5,3294.49 3839.49,3294.49 3849.49,3304.49 v1(3849.49,3432.99)
  Bottom Layer w10: FPC2.2@3689.22,3206.26 3692.01,3209.05 3692.01,3275 v1(3695,3277.99) ; v1(3849.49,3432.99) 3849.49,3443.35 U6.21@3917.08,3510.94
GPIO15: FPC2.3 U6.22 | length 493.9
  Top Layer w10: v1(3665,3277.01) 3665,3285 3691.97,3311.97 3815.53,3311.97 3825.53,3321.97 v1(3825.53,3451.37)
  Bottom Layer w10: v1(3665,3277.01) 3669.53,3272.48 FPC2.3@3669.53,3206.26 ; v1(3825.53,3451.37) 3829.65,3451.37 U6.22@3903.15,3524.87
GPIO16: FPC2.4 U6.23 | length 523.9
  Top Layer w10: v1(3630,3277.01) 3678.98,3325.98 3789.61,3325.98 3799.61,3335.98 v1(3799.61,3467.88)
  Bottom Layer w10: v1(3630,3277.01) 3649.84,3257.16 FPC2.4@3649.84,3206.26 ; v1(3799.61,3467.88) 3809.52,3467.88 3816.64,3475 3825.42,3475 U6.23@3889.22,3538.8
GPIO17: FPC2.5 U6.24 | length 569
  Top Layer w10: v1(3595,3277.01) 3657.99,3340 3770,3340 3780,3350 3780,3443.65 v1(3767.22,3456.43)
  Bottom Layer w10: v1(3595,3277.01) 3630.16,3241.85 FPC2.5@3630.16,3206.26 ; v1(3767.22,3456.43) 3775.57,3464.78 3775.57,3479.72 3848.58,3552.73 U6.24@3875.29,3552.73
K: CN1.8 R3.2 U4.3 | length 329.4
  Bottom Layer w10: CN1.8@3492.16,3669.38 3492.98,3670.19 3525.19,3670.19 3535,3680 3535,3922.91 U4.3@3533.57,3924.34 3533.57,3956.09 R3.2@3529.66,3960
VDD_SPI: C14.2 U6.18 | length 145.7
  Bottom Layer w10: C14.2@3925,3337.56 3925,3435.42 U6.18@3958.8,3469.22
pads on no net: ANT1.1 CN1.14 FPC2.6 FPC2.7 FPC2.8

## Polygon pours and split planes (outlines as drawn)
GND on Bottom Layer (solid, remove dead copper, pour order 4): 3000,4102.82 4495,4102.82 4495,3000 3000,3000
GND on Top Layer (solid, remove dead copper, pour order 0): 3016.1,4097.82 4493.73,4097.82 4493.73,3030.82 3016.1,3030.82
GND on Bottom Layer (solid, remove dead copper, pour order 6): 4370,4097.82 4768.07,4097.82 4768.07,3938.73 4370,3938.73
GND on Top Layer (solid, remove dead copper, pour order 2): 4370,4097.82 4768.07,4097.82 4768.07,3928.73 4370,3928.73

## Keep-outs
Board Outline Layer:
  circle w1: c4709.01,3200.19 r27.56
  circle w10: c4709.01,3200.19 r27.56
  circle w1: c3161.77,3999.4 r27.56
  circle w10: c3161.77,3999.4 r27.56
  region: 3225,3790 3323.43,3790 3323.43,3475.04 3225,3475.04
  region: 3684.21,3733.87 3801.13,3850.8 3895.78,3756.14 3778.86,3639.22
  region: 4440.75,3947.12 4498.84,3998.46 4498.84,4100 4100,4100 4100,3947.12
  lines w1: 3225,3475.04 3323.43,3475.04 3323.43,3790 3225,3790 3225,3475.04
  lines w7.87: 3016.1,3180.82 3016.1,4077.82 cw(c3036.1,4077.82) 3036.1,4097.82 4748.07,4097.82 cw(c4748.07,4077.82) 4768.07,4077.82 4768.07,3180.82 ; 3026.1,3030.82 4738.07,3030.82
  lines w7.9: 3016.1,3180.82 3016.1,3105.82 3016.1,3030.82 3026.1,3030.82 ; 4738.07,3030.82 4769.79,3030.82 4768.07,3180.82

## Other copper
Top Layer:
  region net ADC_VIN: 4166.16,3679.75 4166.16,3669.75 4165.04,3669.66 4163.91,3669.41 4161.68,3668.52 4159.58,3667.25 4157.76,3665.8 4157.76,3683.7 4159.58,3682.25 4161.68,3680.98 4163.91,3680.09 4165.04,3679.84
  region net GPIO0: 4122.5,3679.89 4112.5,3683.62 4112.25,3685.81 4111.59,3687.97 4110.65,3690.05 4109.58,3692.03 4127.09,3688.3 4125.4,3686.68 4123.93,3684.53 4122.89,3682.17 4122.6,3681
  region net GPIO9: 4529.48,3687.59 4525.78,3677.15 4523.69,3679.09 4522.62,3679.91 4521.53,3680.55 4520.42,3680.95 4519.28,3681.07 4518.13,3680.84 4516.96,3680.22 4519.24,3697.66 4521.5,3695.21 4524.26,3692.54
  region net GPIO4: 4517.88,3925 4517.88,3935 4519,3935.09 4520.13,3935.34 4522.37,3936.23 4524.46,3937.5 4526.29,3938.95 4526.29,3921.05 4524.46,3922.5 4522.37,3923.77 4520.13,3924.66 4519,3924.91
  region net GND: 4635.14,3951.93 4628.07,3944.86 4627.21,3945.59 4626.24,3946.21 4624.02,3947.16 4621.65,3947.74 4619.33,3948.01 4631.99,3960.67 4632.26,3958.35 4632.84,3955.98 4633.79,3953.76 4634.41,3952.79
  region net GND: 4659.6,3668.59 4649.6,3668.59 4649.51,3669.71 4649.26,3670.84 4648.37,3673.07 4647.1,3675.17 4645.65,3676.99 4663.55,3676.99 4662.1,3675.17 4660.83,3673.07 4659.94,3670.84 4659.69,3669.71
  region net GND: 4658.14,3413.94 4651.06,3406.86 4650.3,3407.51 4649.54,3407.9 4648.79,3408.1 4648.02,3408.16 4646.34,3408.06 4644.33,3408.01 4656.99,3420.67 4656.94,3418.66 4656.84,3416.98 4656.9,3416.21 4657.1,3415.46 4657.49,3414.7
  region net GPIO6: 3455.14,3586.93 3448.07,3579.86 3447.21,3580.59 3446.24,3581.21 3444.02,3582.16 3441.65,3582.74 3439.33,3583.01 3451.99,3595.67 3452.26,3593.35 3452.84,3590.98 3453.79,3588.76 3454.41,3587.79
  region net GPIO7: 3460.14,3621.93 3453.07,3614.86 3452.21,3615.59 3451.24,3616.21 3449.02,3617.16 3446.65,3617.74 3444.33,3618.01 3456.99,3630.67 3457.26,3628.35 3457.84,3625.98 3458.79,3623.76 3459.41,3622.79
  region net GPIO3: 3366.5,3758.57 3377.31,3755.24 3375.43,3753.19 3374.65,3752.12 3374.03,3751.03 3373.63,3749.91 3373.5,3748.77 3373.69,3747.61 3374.24,3746.43 3357.04,3749.72 3359.76,3751.86 3361.97,3753.92
  region net BL: 3467.43,3713.8 3460.36,3706.73 3459.5,3707.46 3458.52,3708.08 3456.31,3709.03 3453.94,3709.61 3451.62,3709.88 3464.28,3722.54 3464.54,3720.22 3465.13,3717.84 3466.07,3715.63 3466.7,3714.65
  region net GPIO0: 3156.41,3930 3156.41,3920 3155.29,3919.91 3154.16,3919.66 3151.93,3918.77 3149.83,3917.5 3148.01,3916.05 3148.01,3933.95 3149.83,3932.5 3151.93,3931.23 3154.16,3930.34 3155.29,3930.09
  region net $1N3691: 3847.98,3217.7 3844.55,3207.7 3842.35,3207.44 3840.19,3206.76 3838.11,3205.79 3836.14,3204.68 3839.57,3222.25 3841.21,3220.58 3843.35,3219.12 3845.7,3218.09 3846.87,3217.8
  region net DN1: 3288.59,3240 3288.59,3250 3289.71,3250.09 3290.84,3250.34 3293.07,3251.23 3295.17,3252.5 3296.99,3253.95 3296.99,3236.05 3295.17,3237.5 3293.07,3238.77 3290.84,3239.66 3289.71,3239.91
  region net DN1: 3155,3340.59 3145,3346.59 3144.88,3348.87 3144.55,3351.56 3144.08,3354.24 3143.53,3356.45 3159.8,3348.99 3158.77,3348.4 3157.83,3347.59 3157.01,3346.61 3156.32,3345.5 3155.76,3344.3 3155.34,3343.06 3155.09,3341.8
  region net GPIO9: 4141.41,3335 4141.41,3325 4140.29,3324.91 4139.16,3324.66 4136.93,3323.77 4134.83,3322.5 4133.01,3321.05 4133.01,3338.95 4134.83,3337.5 4136.93,3336.23 4139.16,3335.34 4140.29,3335.09
  region net GPIO5: 4408.59,3485 4408.59,3495 4409.71,3495.09 4410.84,3495.34 4413.07,3496.23 4415.17,3497.5 4416.99,3498.95 4416.99,3481.05 4415.17,3482.5 4413.07,3483.77 4410.84,3484.66 4409.71,3484.91
  region net GPIO5: 4236.41,3495 4236.41,3485 4235.29,3484.91 4234.16,3484.66 4231.93,3483.77 4229.83,3482.5 4228.01,3481.05 4228.01,3498.95 4229.83,3497.5 4231.93,3496.23 4234.16,3495.34 4235.29,3495.09
  region net GND: 3505.14,3736.93 3498.07,3729.86 3497.21,3730.59 3496.24,3731.21 3494.02,3732.16 3491.65,3732.74 3489.33,3733.01 3501.99,3745.67 3502.26,3743.35 3502.84,3740.98 3503.79,3738.76 3504.41,3737.79
  region net GND: 3532.87,3664.26 3542.87,3664.26 3542.96,3663.14 3543.21,3662.01 3544.11,3659.77 3545.37,3657.68 3546.82,3655.85 3528.92,3655.85 3530.37,3657.68 3531.64,3659.77 3532.53,3662.01 3532.78,3663.14
  region net $1N3691: 4659.8,3829.75 4649.8,3829.75 ccw(c4631.05,3829.75) 4642.3,3844.75 4667.3,3844.75 ccw(c4678.55,3829.75)
  region net GND: 4633.55,3939.38 4642.52,3944.55 ccw(c4658.43,3965.77) 4658.43,3939.25 4638.85,3923.47 ccw(c4612.33,3923.47)
  region net $1N3691: 4659.8,3557.25 4649.8,3557.25 ccw(c4631.05,3557.25) 4642.3,3572.25 4667.3,3572.25 ccw(c4678.55,3557.25)
  region net $1N3691: 4633.75,3601.98 4640.82,3609.05 ccw(c4656.73,3630.27) 4656.73,3603.75 4639.05,3586.07 ccw(c4612.53,3586.07)
  region net GND: 4649.6,3681.75 4659.6,3681.75 ccw(c4678.35,3681.75) 4667.1,3666.75 4642.1,3666.75 ccw(c4630.85,3681.75)
  region net $1N3691: 4659.8,3284.75 4649.8,3284.75 ccw(c4631.05,3284.75) 4642.3,3299.75 4667.3,3299.75 ccw(c4678.55,3284.75)
  region net $1N3691: 4633.75,3329.48 4640.82,3336.55 ccw(c4656.73,3357.77) 4656.73,3331.25 4639.05,3313.57 ccw(c4612.53,3313.57)
  region net GND: 4649.6,3409.25 4659.6,3409.25 ccw(c4678.35,3409.25) 4667.1,3394.25 4642.1,3394.25 ccw(c4630.85,3409.25)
